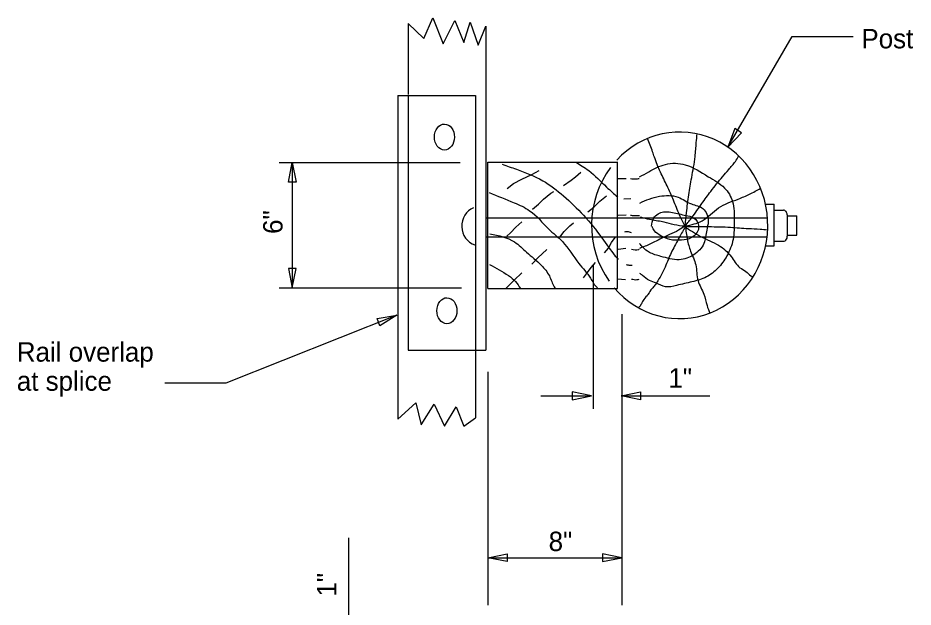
# Model space of a CAD drawing. Extents: x 0 to 34, y 0 to 22.
# Drawn here: x 8.46 to 14.92, y 7.86 to 12.11 of the extents above; entities that cross this region are included whole.
import ezdxf

# ---------------------------------------------------------------- set-up
doc = ezdxf.new("R2010")
doc.units = 0
doc.layers.add('ST_Details', color=7, linetype='Continuous')
doc.layers.add('ST_Text', color=7, linetype='Continuous')

msp = doc.modelspace()

# ---------------------------------------------------------------- linework, layer by layer
at = {"layer": 'ST_Details'}
for p, q in [((11.279363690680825, 12.072612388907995), (11.279363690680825, 11.558612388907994)), ((11.839363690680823, 12.05277905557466), (11.839363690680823, 9.714612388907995)), ((11.20478035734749, 11.553279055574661), (11.20478035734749, 9.216779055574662)), ((11.20478035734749, 11.553279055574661), (11.76478035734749, 11.553279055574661)), ((11.279363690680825, 11.553279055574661), (11.279363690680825, 9.714612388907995)), ((11.76478035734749, 11.553279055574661), (11.76478035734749, 9.226612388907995)), ((11.85378035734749, 11.070445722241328), (12.792197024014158, 11.070445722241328)), ((11.85378035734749, 10.161279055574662), (11.85378035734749, 11.070445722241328)), ((12.791197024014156, 10.161279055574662), (12.791197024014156, 11.071112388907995)), ((12.83703035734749, 10.807945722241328), (12.887113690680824, 10.809612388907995)), ((13.86003035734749, 10.768612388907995), (13.92028035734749, 10.768612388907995)), ((13.92028035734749, 10.468112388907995), (13.92028035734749, 10.768612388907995)), ((13.92028035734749, 10.725945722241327), (13.988697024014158, 10.725945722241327)), ((11.846030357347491, 10.67077905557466), (13.869197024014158, 10.67077905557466)), ((12.79528035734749, 10.688445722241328), (12.851697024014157, 10.692445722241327)), ((13.87278035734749, 10.673945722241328), (13.87278035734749, 10.673945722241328)), ((14.01403035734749, 10.691612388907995), (14.015280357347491, 10.538112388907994)), ((14.01403035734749, 10.68527905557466), (14.085197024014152, 10.68527905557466)), ((14.085197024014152, 10.545112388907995), (14.085197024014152, 10.68527905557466)), ((11.846030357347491, 10.53227905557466), (13.869197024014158, 10.53227905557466)), ((14.015197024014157, 10.545112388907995), (14.085197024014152, 10.545112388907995)), ((13.86003035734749, 10.468112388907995), (13.92028035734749, 10.468112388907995)), ((13.92028035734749, 10.501612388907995), (13.979863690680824, 10.501612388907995)), ((12.79528035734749, 10.443112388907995), (12.849363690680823, 10.451445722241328)), ((12.791197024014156, 10.230779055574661), (12.847530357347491, 10.224112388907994)), ((11.85378035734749, 10.161279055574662), (12.791197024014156, 10.161279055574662)), ((11.279363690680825, 9.714612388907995), (11.76478035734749, 9.714612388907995)), ((11.76478035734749, 9.714612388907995), (11.839363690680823, 9.714612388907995))]:
    msp.add_line(p, q, dxfattribs=at)
for points in [[(11.279363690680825, 12.072612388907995), (11.391780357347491, 11.963779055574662), (11.457113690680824, 12.112112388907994), (11.53178035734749, 11.924279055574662), (11.615780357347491, 12.09227905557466), (11.681113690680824, 11.934279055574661), (11.727780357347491, 12.082445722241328), (11.78378035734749, 11.914445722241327), (11.839363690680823, 12.05277905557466)], [(11.99353035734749, 10.880779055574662), (12.039447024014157, 10.918279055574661), (12.099947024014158, 10.949279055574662), (12.173030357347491, 10.982445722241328), (12.22528035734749, 11.011112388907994)], [(12.400613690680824, 10.902945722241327), (12.454947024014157, 10.942612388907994), (12.488363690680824, 10.966945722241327), (12.525947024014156, 11.000112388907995)], [(12.177197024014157, 10.732612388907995), (12.21903035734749, 10.767945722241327), (12.256613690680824, 10.805612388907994), (12.30878035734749, 10.847612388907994), (12.329613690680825, 10.858779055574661)], [(12.576113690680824, 10.71277905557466), (12.619947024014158, 10.748112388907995), (12.663780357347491, 10.790112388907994), (12.70978035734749, 10.827779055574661)], [(11.991363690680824, 10.538112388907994), (12.01853035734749, 10.562445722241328), (12.056113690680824, 10.60227905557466), (12.099947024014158, 10.642112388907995)], [(12.37353035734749, 10.531445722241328), (12.40478035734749, 10.571279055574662), (12.446613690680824, 10.613279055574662), (12.471697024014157, 10.633112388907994)], [(12.697197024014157, 10.416445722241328), (12.72428035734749, 10.451779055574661), (12.747363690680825, 10.491612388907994), (12.774447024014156, 10.52927905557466)], [(12.173030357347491, 10.334612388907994), (12.214780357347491, 10.381112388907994), (12.279613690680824, 10.44077905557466)], [(12.54478035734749, 10.237445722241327), (12.573947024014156, 10.274945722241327), (12.599113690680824, 10.312612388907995), (12.630363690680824, 10.347945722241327)], [(11.980947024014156, 10.157779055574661), (12.043613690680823, 10.21977905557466), (12.099947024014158, 10.272779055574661)], [(11.20478035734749, 9.216779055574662), (11.33578035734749, 9.335279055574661), (11.373113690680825, 9.177279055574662), (11.466447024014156, 9.325612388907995), (11.541197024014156, 9.167279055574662), (11.625113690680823, 9.30577905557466), (11.681113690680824, 9.167279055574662), (11.76478035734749, 9.226612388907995)]]:
    msp.add_lwpolyline(points, dxfattribs=at)
for centre in [(11.541152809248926, 11.252685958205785), (11.559001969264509, 9.999976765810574)]:
    msp.add_ellipse(centre, major_axis=(0.0004644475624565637, 0.093636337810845), ratio=0.7737824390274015, dxfattribs=at)
for centre, major_axis, ratio, start_param, end_param in [((13.239231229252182, 10.61598293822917), (4.1216114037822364e-17, 0.6731102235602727), 0.9445438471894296, 2.3036393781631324, 7.079119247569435), ((13.239231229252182, 10.61598293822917), (4.1216114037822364e-17, 0.6731102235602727), 0.9445438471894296, 0.9008811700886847, 2.2143986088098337), ((11.799432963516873, 10.610614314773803), (-2.2745364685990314e-17, -0.1414404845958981), 0.9445438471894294, 3.514867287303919, 5.984065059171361), ((13.985942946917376, 10.695657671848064), (1.836368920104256e-18, 0.029990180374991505), 0.9445438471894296, 4.574533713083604, 6.237265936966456), ((13.987051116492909, 10.696465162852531), (-4.793224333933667e-18, -0.0298063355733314), 0.9445438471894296, 1.4313513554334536, 1.4392111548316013), ((13.984822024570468, 10.533254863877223), (-5.240425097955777e-18, -0.03258722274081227), 0.9445438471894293, 6.0937818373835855, 8.002272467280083)]:
    msp.add_ellipse(centre, major_axis=major_axis, ratio=ratio, start_param=start_param, end_param=end_param, dxfattribs=at)
for points in [[(13.277697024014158, 10.615445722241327), (13.288113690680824, 10.706112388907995), (13.304863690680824, 10.836445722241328), (13.325697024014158, 10.960445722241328), (13.35078035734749, 11.112779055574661), (13.359113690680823, 11.212279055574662), (13.365363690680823, 11.276445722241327)], [(13.275613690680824, 10.611112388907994), (13.23803035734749, 10.690612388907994), (13.194113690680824, 10.79677905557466), (13.14828035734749, 10.900612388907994), (13.100197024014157, 11.000112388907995), (13.056363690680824, 11.108445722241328), (13.04378035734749, 11.146112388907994), (13.006197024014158, 11.241112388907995)], [(13.27978035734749, 10.613279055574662), (13.327780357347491, 10.672945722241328), (13.39878035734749, 10.772445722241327), (13.463613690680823, 10.860945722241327), (13.549113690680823, 10.966945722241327), (13.59303035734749, 11.01777905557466), (13.641030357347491, 11.077445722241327), (13.663947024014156, 11.115112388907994)], [(11.958030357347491, 11.057612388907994), (12.06028035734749, 11.020112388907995), (12.25028035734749, 10.938112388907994), (12.400613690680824, 10.827779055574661), (12.54478035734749, 10.688445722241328), (12.678363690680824, 10.524779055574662), (12.774447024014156, 10.394445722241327), (12.794947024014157, 10.369445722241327)], [(12.488363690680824, 11.070945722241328), (12.582363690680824, 11.011112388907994), (12.711863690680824, 10.891779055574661), (12.79203035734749, 10.819612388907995)], [(12.949863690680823, 10.964779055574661), (13.016697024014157, 11.002445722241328), (13.135697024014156, 11.055445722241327), (13.27978035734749, 11.053112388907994), (13.44478035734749, 10.966945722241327), (13.56378035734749, 10.885112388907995), (13.620197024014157, 10.787945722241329), (13.632697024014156, 10.648612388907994), (13.62428035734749, 10.51377905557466), (13.58053035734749, 10.396612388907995), (13.513613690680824, 10.305945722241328), (13.432197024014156, 10.244112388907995), (13.327780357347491, 10.208612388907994), (13.217197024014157, 10.18227905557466), (13.135697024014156, 10.17327905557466), (13.07103035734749, 10.19977905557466), (13.020863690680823, 10.217445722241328), (12.970697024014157, 10.255112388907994), (12.951863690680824, 10.268445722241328)], [(12.79528035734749, 10.953612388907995), (12.845447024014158, 10.953612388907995), (12.85178035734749, 10.953445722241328)], [(12.883113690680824, 10.952612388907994), (12.922697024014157, 10.951445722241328), (12.94778035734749, 10.953612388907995)], [(13.281863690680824, 10.611112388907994), (13.400863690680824, 10.648612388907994), (13.519947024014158, 10.741445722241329), (13.661863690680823, 10.805612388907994), (13.743363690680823, 10.840945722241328), (13.822697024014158, 10.882945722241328)], [(11.864363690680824, 10.851945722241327), (12.043613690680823, 10.779112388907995), (12.156363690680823, 10.721612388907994), (12.29203035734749, 10.591112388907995), (12.392363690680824, 10.498279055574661), (12.511363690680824, 10.341445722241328), (12.594947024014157, 10.235112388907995), (12.642863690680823, 10.166779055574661), (12.65128035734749, 10.159945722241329)], [(12.951863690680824, 10.77677905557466), (13.01878035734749, 10.805612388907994), (13.093947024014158, 10.825445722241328), (13.22753035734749, 10.818945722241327), (13.323613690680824, 10.770279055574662), (13.407197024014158, 10.736945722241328), (13.44478035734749, 10.64427905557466), (13.43428035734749, 10.580112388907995), (13.413447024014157, 10.485112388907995), (13.340363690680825, 10.40327905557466), (13.235947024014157, 10.367945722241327), (13.10228035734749, 10.392112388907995), (13.020863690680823, 10.420945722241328), (12.972863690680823, 10.458445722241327), (12.949863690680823, 10.485112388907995)], [(12.883113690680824, 10.689445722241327), (12.910197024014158, 10.68627905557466), (12.949863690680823, 10.68627905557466)], [(13.275613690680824, 10.608779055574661), (13.198363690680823, 10.619945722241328), (13.127363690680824, 10.637612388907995), (13.035447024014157, 10.655279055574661), (12.977030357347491, 10.668445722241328), (12.956113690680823, 10.675112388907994)], [(13.035447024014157, 10.608779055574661), (13.050113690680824, 10.66627905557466), (13.083447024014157, 10.699445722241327), (13.162863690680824, 10.71277905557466), (13.258947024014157, 10.692779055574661), (13.354947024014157, 10.657445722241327), (13.375863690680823, 10.59777905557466), (13.323613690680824, 10.527112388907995), (13.252613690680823, 10.50927905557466), (13.16703035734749, 10.51377905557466), (13.10228035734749, 10.540279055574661), (13.058447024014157, 10.575612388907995), (13.039613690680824, 10.608779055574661)], [(13.281863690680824, 10.608779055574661), (13.235947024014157, 10.52927905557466), (13.208780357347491, 10.478279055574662), (13.160780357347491, 10.381112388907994), (13.139863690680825, 10.328112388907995), (13.081363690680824, 10.215279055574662), (13.06053035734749, 10.184445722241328), (13.039613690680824, 10.159945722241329), (13.010447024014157, 10.117945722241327), (12.981197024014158, 10.080445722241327), (12.962363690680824, 10.049445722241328), (12.949863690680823, 10.029612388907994), (12.943613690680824, 10.02527905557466)], [(13.275613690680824, 10.611112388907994), (13.231697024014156, 10.580112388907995), (13.164947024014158, 10.549112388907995), (13.056363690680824, 10.496112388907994), (12.979113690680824, 10.460779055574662), (12.949863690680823, 10.449612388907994)], [(13.275613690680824, 10.608779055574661), (13.390447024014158, 10.535779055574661), (13.519947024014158, 10.471779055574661), (13.609697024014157, 10.392112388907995), (13.674447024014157, 10.310445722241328), (13.716197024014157, 10.283945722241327), (13.753780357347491, 10.250612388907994), (13.770530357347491, 10.241945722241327)], [(13.27978035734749, 10.608779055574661), (13.448947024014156, 10.606612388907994), (13.60553035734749, 10.60227905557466), (13.73503035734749, 10.59327905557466), (13.820613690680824, 10.588945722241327), (13.870697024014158, 10.584612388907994)], [(13.27978035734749, 10.608779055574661), (13.294447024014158, 10.51377905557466), (13.317363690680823, 10.429779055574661), (13.354947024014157, 10.33027905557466), (13.371697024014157, 10.215279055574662), (13.413447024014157, 10.120279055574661), (13.436363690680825, 10.038445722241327), (13.457280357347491, 9.980945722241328)], [(11.869697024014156, 10.55427905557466), (12.047697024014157, 10.496112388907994), (12.133363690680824, 10.423112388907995), (12.239947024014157, 10.328112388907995), (12.298363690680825, 10.250612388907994), (12.333863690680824, 10.17327905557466), (12.34428035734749, 10.157779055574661)], [(12.842947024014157, 10.568945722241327), (12.860113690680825, 10.571279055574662), (12.889697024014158, 10.564112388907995)], [(12.890947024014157, 10.443112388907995), (12.891363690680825, 10.443112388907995), (12.94153035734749, 10.44077905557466), (12.94778035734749, 10.443112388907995)], [(11.86753035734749, 10.332279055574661), (12.003947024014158, 10.252945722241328), (12.054030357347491, 10.210945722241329), (12.08953035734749, 10.159945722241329)], [(12.853947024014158, 10.333612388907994), (12.878863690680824, 10.328112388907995), (12.895363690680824, 10.329779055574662)], [(12.891363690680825, 10.228445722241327), (12.93103035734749, 10.224112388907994), (12.945697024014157, 10.226445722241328)]]:
    msp.add_spline(points, degree=3, dxfattribs=at)
at = {"layer": 'ST_Text'}
for p, q in [((10.34853035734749, 11.068279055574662), (11.654613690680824, 11.068279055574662)), ((10.44303035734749, 11.068279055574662), (10.44303035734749, 10.490612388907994)), ((10.44303035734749, 10.490612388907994), (10.44303035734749, 10.163945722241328)), ((12.61403035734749, 10.326612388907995), (12.61403035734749, 9.291612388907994)), ((10.34853035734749, 10.163945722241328), (11.663447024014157, 10.163945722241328)), ((12.821613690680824, 9.975612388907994), (12.821613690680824, 8.301112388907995)), ((11.85378035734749, 9.558445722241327), (11.85378035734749, 8.301112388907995)), ((12.23753035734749, 9.386112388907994), (12.602363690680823, 9.386112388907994)), ((12.815947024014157, 9.386112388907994), (13.45684563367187, 9.386112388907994)), ((10.849113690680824, 8.36219289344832), (10.849113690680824, 7.708612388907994)), ((11.85378035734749, 8.301112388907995), (11.85378035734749, 7.875779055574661)), ((12.821613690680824, 8.301112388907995), (12.821613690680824, 7.875779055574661)), ((11.854863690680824, 8.217945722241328), (12.821613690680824, 8.217945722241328))]:
    msp.add_line(p, q, dxfattribs=at)
for points in [[(13.586197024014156, 11.18002905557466), (14.051947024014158, 11.978945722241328), (14.491197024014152, 11.978945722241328)], [(11.196530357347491, 9.967362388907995), (9.963113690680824, 9.477112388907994), (9.52378035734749, 9.477112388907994)]]:
    msp.add_lwpolyline(points, dxfattribs=at)
for points in [[(13.636640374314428, 11.313593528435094), (13.586197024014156, 11.18002905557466), (13.68413106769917, 11.283918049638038)], [(10.415028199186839, 10.928279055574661), (10.44302819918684, 11.068279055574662), (10.47102819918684, 10.928279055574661)], [(10.41503035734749, 10.303945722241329), (10.44303035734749, 10.163945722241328), (10.471030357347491, 10.303945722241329)], [(11.055794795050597, 9.943331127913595), (11.196530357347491, 9.967362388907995), (11.075863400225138, 9.891050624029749)], [(12.462363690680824, 9.358112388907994), (12.602363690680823, 9.386112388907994), (12.462363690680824, 9.414112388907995)], [(12.955947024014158, 9.358112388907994), (12.815947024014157, 9.386112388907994), (12.955947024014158, 9.414112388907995)], [(11.994863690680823, 8.189945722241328), (11.854863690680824, 8.217945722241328), (11.994863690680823, 8.245945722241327)], [(12.681613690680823, 8.189831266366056), (12.821613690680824, 8.217831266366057), (12.681613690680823, 8.245831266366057)]]:
    msp.add_lwpolyline(points, close=True, dxfattribs=at)

# ---------------------------------------------------------------- texts
for s, p in [('Post', (14.550560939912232, 11.89254488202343)), ('Rail overlap', (8.45475520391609, 9.632634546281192)), ('at splice', (8.45475520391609, 9.422634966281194)), ('1"', (13.157833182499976, 9.445041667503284)), ('8" ', (12.293324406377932, 8.266307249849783))]:
    msp.add_text(s, height=0.13999972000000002, dxfattribs=at).set_placement(p)
for s, p in [('6" ', (10.372817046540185, 10.554025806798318)), ('1" ', (10.761621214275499, 7.937996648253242))]:
    msp.add_text(s, height=0.13999972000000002, rotation=89.99999999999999, dxfattribs=at).set_placement(p)

doc.saveas('drawing.dxf')
